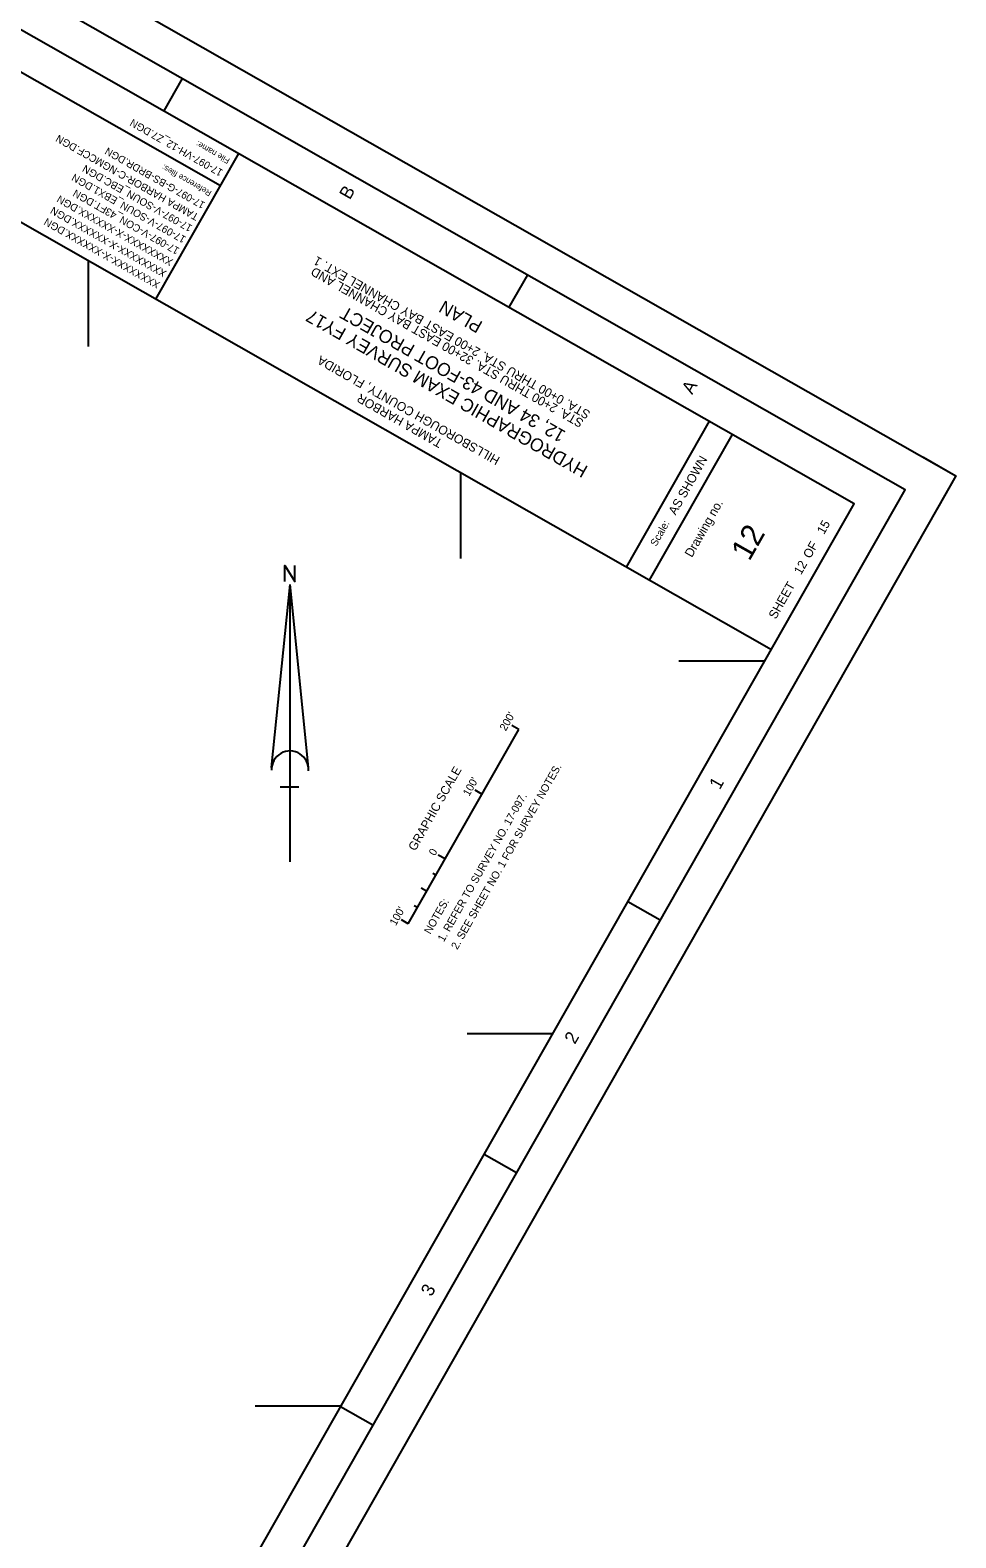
# Model space of a CAD drawing. Extents: x 515534 to 520665, y 1298425 to 1303930.
# Drawn here: x 519422 to 520665, y 1300823 to 1302847 of the extents above; entities that cross this region are included whole.
import ezdxf

# ---------------------------------------------------------------- set-up
doc = ezdxf.new("R2010")
doc.units = 0
for name, color, linetype in [('G-ANNO-NPLT', 7, 'Continuous'), ('G-ANNO-TEXT-DRWG', 7, 'Continuous'), ('G-ANNO-TEXT-PROJ', 7, 'Continuous'), ('G-ANNO-TEXT-TTLB', 7, 'Continuous'), ('G-ANNO-TTLB', 7, 'Continuous'), ('V-ANNO-NOTE', 7, 'Continuous'), ('V-ANNO-SYMB', 7, 'Continuous'), ('V-TOPO-COOR-STAT', 7, 'Continuous')]:
    doc.layers.add(name, color=color, linetype=linetype)

msp = doc.modelspace()

# ---------------------------------------------------------------- linework, layer by layer
at = {"layer": 'G-ANNO-NPLT'}
msp.add_lwpolyline([(515533.7, 1300105.7), (517709.3, 1303930.2), (520664.6, 1302249.1), (518489, 1298424.6)], close=True, dxfattribs=at)
msp.add_lwpolyline([(520621.2, 1302273.9), (520664.7, 1302249.2), (520639.9, 1302205.7)], dxfattribs=at)
at = {"layer": 'G-ANNO-TTLB'}
for p, q in [((517635.5, 1303598.2), (520417, 1302016)), ((519372, 1302812.6), (519677.4, 1302638.8)), ((519625.9, 1302782.4), (519601.1, 1302739)), ((519590.6, 1302486.1), (519701.8, 1302681.7)), ((520089.4, 1302518.7), (520064.7, 1302475.3)), ((520222.5, 1302126.6), (520333.7, 1302322.2)), ((520253.5, 1302109), (520364.8, 1302304.6)), ((520267.6, 1301652.3), (520224.1, 1301677)), ((520074.8, 1301313.3), (520031.3, 1301338)), ((519881.9, 1300974.3), (519838.5, 1300999.1))]:
    msp.add_line(p, q, dxfattribs=at)
for points in [[(518470.3, 1298492.8), (520596.4, 1302230.3), (517728, 1303862), (515601.9, 1300124.4)], [(517746.8, 1303793.8), (515707.2, 1300208.3), (518488.6, 1298626.1), (520528.2, 1302211.6)]]:
    msp.add_lwpolyline(points, close=True, dxfattribs=at)
at = {"layer": 'V-ANNO-NOTE'}
for p, q in [((519929.4, 1301647.7), (520077.7, 1301908.5)), ((520077.7, 1301908.5), (520068.6, 1301913.7)), ((520028.2, 1301821.6), (520019.2, 1301826.8)), ((519978.8, 1301734.7), (519969.7, 1301739.8)), ((519978.8, 1301734.7), (519969.7, 1301739.8)), ((519978.8, 1301734.7), (519974.5, 1301737.1)), ((519966.4, 1301712.9), (519962.3, 1301715.3)), ((519954.1, 1301691.2), (519946.7, 1301695.4)), ((519941.7, 1301669.5), (519937.6, 1301671.8)), ((519929.4, 1301647.7), (519920.3, 1301652.9))]:
    msp.add_line(p, q, dxfattribs=at)
at = {"layer": 'V-ANNO-SYMB'}
for p, q in [((519746, 1301857.3), (519770.7, 1302103)), ((519770.7, 1301730.7), (519770.7, 1302103)), ((519795.4, 1301857.3), (519770.7, 1302103)), ((519782.4, 1301831.2), (519757.6, 1301831.2))]:
    msp.add_line(p, q, dxfattribs=at)
msp.add_lwpolyline([(519763.8, 1302107), (519763.8, 1302128.7), (519777.3, 1302107), (519777.3, 1302128.7)], dxfattribs=at)
msp.add_arc((519770.7, 1301854.8), 24.8, 355.2984, 182.0673, dxfattribs=at)
at = {"layer": 'V-TOPO-COOR-STAT'}
for p, q in [((519500, 1302422.6), (519500, 1302537.6)), ((520000, 1302138.1), (520000, 1302253.2)), ((520407.9, 1302000), (520292.8, 1302000)), ((520123.4, 1301500), (520008.4, 1301500)), ((519839, 1301000), (519724, 1301000))]:
    msp.add_line(p, q, dxfattribs=at)

# ---------------------------------------------------------------- texts
at = {"layer": 'G-ANNO-TEXT-DRWG'}
for s, height, rotation, p in [('17-097-VH-12_Z7.DGN', 10, 150.3667, (519681.6, 1302659.1)), ('TAMPA HARBOR-C-NGMCCF.DGN', 10, 150.3667, (519649.1, 1302599.8)), ('17-097-V-SOUN_EBX1.DGN', 10, 150.3667, (519631.8, 1302569.4)), ('17-097-V-SOUN_EBC.DGN', 10, 150.3667, (519640.4, 1302584.6)), ('17-097-V-CON_43FT.DGN', 10, 150.3667, (519623.1, 1302554.2)), ('XXXXXXXX-X-XXXXXX.DGN', 10, 150.3667, (519614.5, 1302539)), ('XXXXXXXX-X-XXXXXX.DGN', 10, 150.3667, (519597.2, 1302508.5)), ('XXXXXXXX-X-XXXXXX.DGN', 10, 150.3667, (519605.8, 1302523.7)), ('STA. 0+00 THRU STA. 2+00 EAST BAY CHANNEL EXT. 1', 12, 150.3667, (520175, 1302334.9)), ('STA. 2+00 THRU STA. 32+00 EAST BAY CHANNEL AND ', 12, 150.3667, (520166, 1302323.5)), ('PLAN', 17.5, 150.3667, (520030.7, 1302455)), (' 12          15', 12, 60.3667, (520454.6, 1302111.4)), ('12', 30, 60.3667, (520387.4, 1302133.4))]:
    msp.add_text(s, height=height, rotation=rotation, dxfattribs=at).set_placement(p)
at = {"layer": 'G-ANNO-TEXT-PROJ'}
for s, height, p in [('17-097-G-BS-BRDR.DGN', 9.8, (519657.5, 1302615.4)), ('HYDROGRAPHIC EXAM SURVEY FY17', 17.5, (520172, 1302260.9)), ('12, 34 AND 43-FOOT PROJECT', 17.5, (520142.1, 1302308.1)), ('HILLSBOROUGH COUNTY, FLORIDA', 12, (520053.6, 1302273.3)), ('TAMPA HARBOR', 12, (519976.6, 1302296.4))]:
    msp.add_text(s, height=height, rotation=150.3667, dxfattribs=at).set_placement(p)
at = {"layer": 'G-ANNO-TEXT-TTLB'}
for s, height, rotation, p in [('File name:', 8, 150.3667, (519690.7, 1302674.3)), ('Reference files:', 8, 150.3667, (519666.2, 1302630.8)), ('AS SHOWN', 12, 60.3667, (520288.4, 1302195.5)), ('Drawing no.', 12, 60.3667, (520310.3, 1302138.6)), ('Scale:', 10, 60.3667, (520262.4, 1302153.5)), ('SHEET         OF', 12, 60.3667, (520422.9, 1302055.7))]:
    msp.add_text(s, height=height, rotation=rotation, dxfattribs=at).set_placement(p)
at = {"layer": 'G-ANNO-TTLB'}
for s, p in [('B', (519851, 1302618.7)), ('A', (520310.6, 1302357.3)), ('1', (520347.6, 1301826.6)), ('2', (520153.2, 1301484.9)), ('3', (519960.5, 1301146.1))]:
    msp.add_text(s, height=17.5, rotation=60.3667, dxfattribs=at).set_placement(p)
at = {"layer": 'V-ANNO-NOTE'}
for s, height, p in [("200'", 10.42, (520060.4, 1301905.6)), ('GRAPHIC SCALE', 11.666, (519938.9, 1301744.5)), ('2. SEE SHEET NO. 1 FOR SURVEY NOTES.', 10.416, (519995.3, 1301612.2)), ("100'", 10.42, (520011.1, 1301818)), ('1. REFER TO SURVEY NO. 17-097.', 10.416, (519977.2, 1301622.5)), ('0', 10.4, (519965.3, 1301738.1)), ('NOTES:', 10.42, (519959.1, 1301632.8)), ("100'", 10.42, (519912.7, 1301644.2))]:
    msp.add_text(s, height=height, rotation=60.3667, dxfattribs=at).set_placement(p)

doc.saveas('drawing.dxf')
